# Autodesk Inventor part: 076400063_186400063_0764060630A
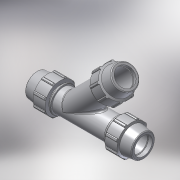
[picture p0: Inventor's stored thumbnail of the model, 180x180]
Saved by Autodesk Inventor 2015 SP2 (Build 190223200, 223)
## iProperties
Created: 2017-02
Part Number: 076400063_186400063_0764060630A
Material: PVC-Piping
Description: PLASSON 45° TEE 63-63-63
Document SubType Name: Modeling
Designer: KIM
Mass: 92.6774 g
Surface Area: 199.44 cm^2
Volume: 66.1981 cm^3
Density: 1.4 g/cm^3
Appearance: Smooth - White
Author: Кирилл
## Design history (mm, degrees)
derived "07640.ipt"
feature "Solid1::07640.ipt"
feature "Solid3::07640.ipt"
tag "TaggingFeature1"
body "Solid1"
other parameters: "d2" = 63, "d4" = 15.58333, "d5" = 37.4, "d7" = 113, "d11" = 6.23333, "d13" = 120 deg, "d14" = 81.9, "d15" = 8 deg, "d16" = 90.4, "d18" = 3.15, "d19" = 35 deg, "d20" = 17.5 deg, "d21" = 105.09, "d23" = 0, "d25" = 360 deg, "d27" = 2.26, "d33" = 1.26, "d42" = 44.88, "d43" = 3.39, "d46" = 1.89, "d68" = 5.61, "d91" = 79.1, "d95" = 56.7, "d134" = 187, "d138" = 45 deg, "d141" = 207, "d144" = 0, "d146" = 0, "d150" = 3.15, "d158" = 6.3, "d165" = 242, "d166" = 105.09, "d167" = 35 deg, "d168" = 17.5 deg, "d170" = 0, "d172" = 360 deg, "d174" = 3.39, "d177" = 2.26, "d_" = 63, "E_" = 113, "A_" = 207, "H_" = 374
